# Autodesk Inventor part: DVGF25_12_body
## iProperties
Created: 2010-04
Part Number: DVGF25_12_body
Document SubType Name: Modeling
Designer: TB
Mass: 155.863 g
Surface Area: 494.446 cm^2
Volume: 155.863 cm^3
Density: 1 g/cm^3
Author: TB
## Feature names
1. Kropp [Revolution]
2. Chamfer
3. Extrusion2
4. Hole1
5. Revolution2
6. Hole2
7. Fillet1
8. Extrusion3
9. Hole3
